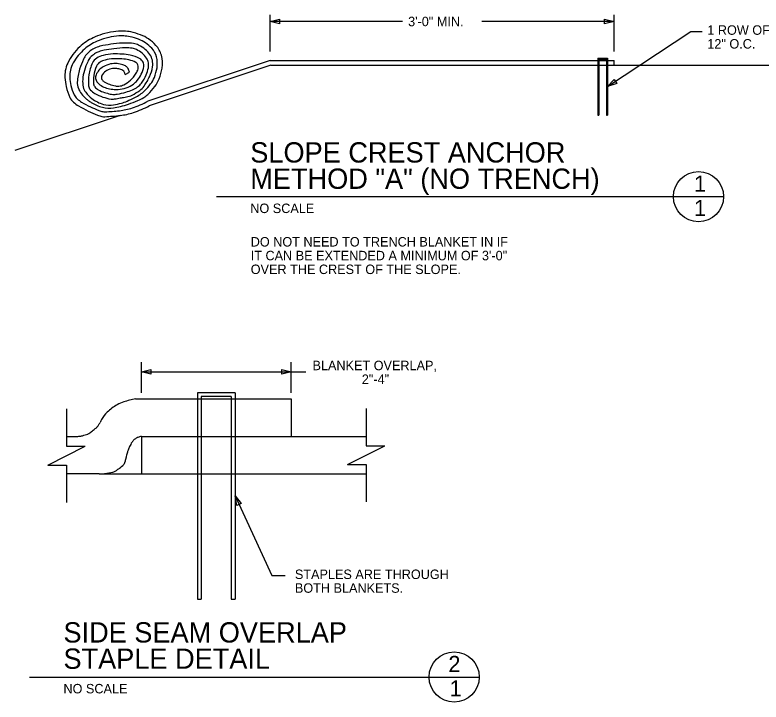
# Model space of a CAD drawing. Extents: x 27123946 to 27124151, y 1145898 to 1146027.
# Drawn here: x 27124034.8 to 27124100.1, y 1145966.8 to 1146026.9 of the extents above; entities that cross this region are included whole.
import ezdxf

# ---------------------------------------------------------------- set-up
doc = ezdxf.new("R2010")
doc.units = 0
for name, color, linetype in [('C-PVMT', 7, 'Continuous'), ('Default', 7, 'Continuous'), ('G-ANNO-CELL', 7, 'Continuous'), ('G-ANNO-TEXT', 7, 'Continuous'), ('G-ANNO-TTXT', 7, 'Continuous'), ('L-SITE-SOIL', 7, 'Continuous')]:
    doc.layers.add(name, color=color, linetype=linetype)

msp = doc.modelspace()

# ---------------------------------------------------------------- linework, layer by layer
at = {"layer": 'C-PVMT'}
for p, q in [((27124057.171, 1146022.891), (27124046.46, 1146019.32)), ((27124057.171, 1146022.891), (27124087.272, 1146022.891)), ((27124087.272, 1146022.474), (27124087.272, 1146022.891)), ((27124057.239, 1146022.474), (27124046.592, 1146018.925)), ((27124057.239, 1146022.474), (27124087.272, 1146022.474)), ((27124087.272, 1146022.474), (27124102.27, 1146022.474)), ((27124045.386, 1145993.286), (27124059.017, 1145993.286)), ((27124059.017, 1145993.286), (27124059.017, 1145990.007)), ((27124039.344, 1145990.007), (27124040.349, 1145990.007)), ((27124045.902, 1145990.007), (27124045.902, 1145986.728)), ((27124045.902, 1145990.007), (27124065.575, 1145990.007)), ((27124042.214, 1145986.728), (27124039.344, 1145986.728)), ((27124045.902, 1145986.728), (27124065.575, 1145986.728))]:
    msp.add_line(p, q, dxfattribs=at)
msp.add_lwpolyline([(27124044.483, 1146021.655), (27124044.849, 1146021.855)], dxfattribs=at)
for centre, radius, start, end in [((27124044.192, 1146020.388), 5.071, 88.01317, 98.4237), ((27124044.253, 1146022.165), 3.292, 77.32435, 88.01317), ((27124043.73, 1146020.422), 4.896, 114.76664, 123.00696), ((27124044.596, 1146018.544), 6.964, 107.85911, 114.76664), ((27124044.353, 1146019.301), 6.17, 98.4237, 107.85911), ((27124044.343, 1146019.319), 5.728, 98.4237, 107.91848), ((27124044.177, 1146020.443), 4.592, 87.81603, 98.4237), ((27124044.234, 1146021.946), 3.088, 77.32435, 87.81603), ((27124043.605, 1146019.151), 5.953, 69.77358, 77.32435), ((27124043.442, 1146018.559), 6.988, 69.99356, 77.32435), ((27124044.773, 1146022.213), 3.1, 55.57154, 69.99356), ((27124043.081, 1146021.421), 3.705, 123.00696, 134.07939), ((27124043.161, 1146021.322), 3.408, 123.04587, 134.07939), ((27124043.716, 1146020.469), 4.427, 114.76664, 123.04587), ((27124044.571, 1146018.617), 6.466, 107.91848, 114.76664), ((27124043.345, 1146020.137), 4.128, 101.30557, 108.71255), ((27124044.996, 1146011.877), 12.551, 97.05967, 101.30557), ((27124044.742, 1146013.929), 10.484, 91.16867, 97.05967), ((27124044.612, 1146020.316), 4.095, 81.73672, 91.16867), ((27124044.984, 1146022.876), 1.508, 63.44395, 81.73672), ((27124044.222, 1146021.353), 3.211, 50.9357, 63.44395), ((27124044.725, 1146022.19), 2.714, 55.57154, 69.77358), ((27124044.441, 1146021.776), 3.216, 42.53148, 55.57154), ((27124044.391, 1146021.655), 3.776, 42.50986, 55.57154), ((27124045.63, 1146022.792), 2.094, 15.07414, 42.50986), ((27124044.593, 1146019.86), 5.879, 134.07939, 142.86493), ((27124044.42, 1146020.022), 5.218, 134.07939, 142.99163), ((27124042.999, 1146021.746), 2.52, 124.95777, 138.85316), ((27124042.613, 1146022.297), 1.847, 108.71255, 124.95777), ((27124042.709, 1146022.16), 1.583, 109.22732, 124.81411), ((27124043.297, 1146020.472), 3.37, 101.30557, 109.22732), ((27124044.963, 1146012.14), 11.868, 97.08628, 101.30557), ((27124044.717, 1146014.117), 9.875, 91.16867, 97.08628), ((27124044.584, 1146020.668), 3.323, 80.95875, 91.16867), ((27124044.908, 1146022.707), 1.259, 63.44395, 80.95875), ((27124044.194, 1146021.279), 2.855, 51.84003, 63.44395), ((27124044.862, 1146022.129), 1.774, 33.18872, 51.84003), ((27124045.006, 1146022.319), 1.967, 33.18872, 50.9357), ((27124045.493, 1146022.74), 1.79, 15.07414, 42.53148), ((27124043.134, 1146020.965), 4.048, 142.86493, 155.21623), ((27124043.175, 1146020.961), 3.659, 142.99163, 155.21623), ((27124046.639, 1146020.26), 6.418, 154.79019, 163.13314), ((27124042.432, 1146022.241), 1.767, 138.85316, 154.79019), ((27124042.521, 1146022.16), 1.457, 138.27281, 154.79019), ((27124043.015, 1146021.72), 2.12, 124.81411, 138.27281), ((27124042.51, 1146022.256), 0.984, 121.665, 154.7137), ((27124043.022, 1146021.425), 1.961, 104.03089, 121.665), ((27124043.104, 1146021.422), 1.548, 104.03089, 121.89178), ((27124043.594, 1146019.136), 4.32, 92.17654, 104.03089), ((27124043.632, 1146019.31), 3.725, 92.54328, 104.03089), ((27124043.696, 1146016.46), 6.998, 85.81664, 92.17654), ((27124043.745, 1146016.772), 6.267, 85.81664, 92.54328), ((27124043.881, 1146018.641), 4.392, 77.78001, 85.81664), ((27124043.754, 1146017.259), 6.197, 79.05759, 85.81664), ((27124044.336, 1146020.739), 2.245, 61.56669, 77.78001), ((27124044.392, 1146020.556), 2.838, 61.56669, 79.05759), ((27124045.386, 1146022.392), 0.751, 27.17705, 61.56669), ((27124045.395, 1146022.477), 1.138, 9.83943, 33.18872), ((27124045.39, 1146022.57), 1.509, 12.9005, 33.18872), ((27124045.406, 1146022.574), 1.493, 350.21375, 12.9005), ((27124045.006, 1146022.609), 2.293, 350.86974, 15.07414), ((27124045.092, 1146022.647), 2.652, 350.74384, 15.07414), ((27124042.039, 1146021.47), 2.842, 155.21623, 169.96936), ((27124042.085, 1146021.464), 2.459, 155.21623, 170.14213), ((27124046.257, 1146020.401), 5.587, 154.79019, 163.20405), ((27124045.016, 1146021.072), 3.756, 154.7137, 171.45509), ((27124044.592, 1146021.156), 2.891, 154.7137, 172.02722), ((27124043.273, 1146021.06), 1.453, 119.22733, 157.15829), ((27124042.719, 1146022.04), 0.821, 121.89178, 154.7137), ((27124043.767, 1146020.179), 2.463, 103.12908, 119.22733), ((27124043.591, 1146020.932), 1.69, 83.66587, 103.12908), ((27124043.575, 1146020.781), 1.411, 82.38454, 103.12908), ((27124043.484, 1146020.101), 2.098, 72.65231, 82.38454), ((27124043.476, 1146019.9), 2.729, 72.65231, 83.66587), ((27124043.996, 1146021.564), 0.985, 54.27413, 72.65231), ((27124044.252, 1146021.92), 0.547, 28.62008, 54.27413), ((27124043.752, 1146021.647), 1.116, 10.7423, 28.62008), ((27124045.192, 1146022.321), 0.447, 24.72089, 61.56669), ((27124044.385, 1146022.445), 1.262, 331.98323, 351.46573), ((27124045.197, 1146022.323), 0.441, 351.46573, 24.72089), ((27124044.05, 1146022.66), 2.09, 331.97737, 351.46573), ((27124045.487, 1146022.444), 0.637, 351.46573, 27.17705), ((27124043.773, 1146022.758), 2.788, 335.97186, 349.37647), ((27124045.33, 1146022.466), 1.204, 349.37647, 9.83943), ((27124043.479, 1146022.906), 3.448, 335.34299, 350.21375), ((27124043.324, 1146022.879), 3.997, 338.42088, 350.86974), ((27124043.18, 1146022.958), 4.589, 338.42088, 350.74384), ((27124041.708, 1146021.529), 2.506, 169.96936, 183.18108), ((27124041.843, 1146021.506), 2.213, 170.14213, 183.18108), ((27124045.334, 1146020.656), 5.054, 163.13314, 176.09788), ((27124044.38, 1146020.968), 3.626, 163.20405, 176.09788), ((27124045.112, 1146021.058), 3.853, 171.45509, 185.71297), ((27124044.728, 1146021.137), 3.029, 172.02722, 185.71297), ((27124042.497, 1146021.387), 0.611, 157.15829, 217.30688), ((27124042.713, 1146021.406), 0.316, 155.54752, 213.89266), ((27124043.32, 1146021.129), 0.984, 123.45944, 155.54752), ((27124043.588, 1146020.725), 1.469, 103.12908, 123.45944), ((27124043.917, 1146021.487), 0.646, 55.06127, 72.65231), ((27124044.069, 1146021.705), 0.38, 28.62008, 55.06127), ((27124043.739, 1146021.525), 0.755, 9.9512, 28.62008), ((27124043.639, 1146022.842), 2.108, 320.99808, 331.98323), ((27124042.966, 1146023.236), 3.318, 320.99808, 331.97737), ((27124042.639, 1146023.263), 4.029, 324.28256, 335.97186), ((27124043.99, 1146021.656), 4.791, 183.18108, 192.72566), ((27124043.738, 1146021.611), 4.111, 183.18108, 192.73794), ((27124041.503, 1146020.917), 1.213, 176.09788, 202.74147), ((27124043.018, 1146021.061), 2.261, 176.09788, 192.44727), ((27124043.152, 1146021.886), 1.434, 217.30688, 236.98642), ((27124043.042, 1146021.627), 0.714, 213.89266, 236.98642), ((27124043.871, 1146022.902), 2.234, 236.98642, 249.97615), ((27124043.074, 1146023.247), 2.799, 297.29053, 311.87733), ((27124042.903, 1146023.438), 3.054, 311.87733, 320.99808), ((27124044.141, 1146022.285), 1.807, 306.10024, 320.99808), ((27124044.778, 1146021.725), 1.395, 304.35108, 324.28256), ((27124041.951, 1146023.607), 5.129, 324.69625, 335.34299), ((27124044.88, 1146022.264), 2.324, 322.07314, 338.42088), ((27124044.851, 1146022.298), 2.792, 322.60426, 338.42088), ((27124043.77, 1146021.606), 4.566, 192.72566, 205.28648), ((27124043.56, 1146021.571), 3.929, 192.73794, 205.28648), ((27124042.469, 1146021.323), 2.261, 202.74147, 216.58396), ((27124042.02, 1146020.84), 1.239, 192.44727, 216.58396), ((27124041.908, 1146020.737), 0.633, 185.71297, 221.37557), ((27124042.641, 1146021.383), 1.61, 221.37557, 240.02803), ((27124042.184, 1146020.882), 0.472, 185.71297, 220.84709), ((27124042.727, 1146021.352), 1.19, 220.84709, 240.02803), ((27124043.481, 1146022.659), 2.699, 240.02803, 252.72996), ((27124043.272, 1146022.072), 1.655, 236.98642, 255.28955), ((27124043.847, 1146024.262), 3.92, 255.28955, 263.48133), ((27124044.313, 1146024.115), 3.525, 249.97615, 258.69431), ((27124043.711, 1146023.071), 2.721, 263.48133, 273.31692), ((27124043.845, 1146021.774), 1.138, 258.69431, 274.06786), ((27124043.719, 1146022.946), 2.596, 273.31692, 289.43288), ((27124043.847, 1146021.75), 1.113, 274.06786, 297.29053), ((27124043.325, 1146024.327), 4.387, 286.19691, 294.29613), ((27124043.774, 1146022.788), 2.428, 289.43288, 306.10024), ((27124043.16, 1146023.847), 4.429, 295.74168, 305.889), ((27124043.958, 1146022.925), 2.849, 294.29613, 304.35108), ((27124044.787, 1146021.599), 1.654, 305.889, 324.69625), ((27124044.498, 1146021.902), 2.37, 303.16369, 314.98885), ((27124041.516, 1146024.886), 6.589, 314.98885, 322.07314), ((27124041.637, 1146024.754), 6.837, 314.98885, 322.60426), ((27124040.81, 1146020.208), 1.293, 205.28648, 229.01589), ((27124041.033, 1146020.377), 1.133, 205.28648, 228.76652), ((27124042.686, 1146021.484), 2.532, 216.58396, 229.66278), ((27124043.205, 1146021.72), 2.715, 216.58396, 232.82115), ((27124043.504, 1146022.88), 3.337, 240.02803, 252.95174), ((27124045.475, 1146029.307), 10.06, 252.95174, 257.20054), ((27124044.603, 1146026.269), 6.479, 252.72996, 257.20054), ((27124043.479, 1146021.324), 1.408, 257.20054, 266.79957), ((27124043.498, 1146021.649), 1.734, 266.79957, 279.72386), ((27124016.101, 1146180.507), 163.31, 279.72386, 279.8907), ((27124042.627, 1146026.731), 6.89, 279.72386, 286.19691), ((27124018.195, 1146168.499), 151.122, 279.8907, 279.96049), ((27123987.161, 1146345.212), 330.539, 279.96049, 280.00768), ((27124044.281, 1146021.523), 1.849, 280.00768, 295.74168), ((27124040.926, 1146028.186), 9.608, 292.78471, 297.2069), ((27124042.897, 1146024.352), 5.297, 297.2069, 303.16369), ((27124043.611, 1146024.022), 5.041, 293.11244, 299.7131), ((27124045.264, 1146021.126), 1.707, 299.7131, 314.98885), ((27124042.017, 1146021.597), 3.133, 229.01589, 239.04615), ((27124042.051, 1146021.539), 2.679, 228.76652, 239.04615), ((27124045.111, 1146026.64), 8.627, 239.04615, 244.76938), ((27124043.511, 1146022.455), 3.806, 229.66278, 233.56372), ((27124044.294, 1146023.516), 5.124, 233.56372, 236.92561), ((27124043.234, 1146021.889), 3.182, 236.92561, 256.43473), ((27124043.454, 1146022.049), 3.128, 232.82115, 253.66996), ((27124043.122, 1146020.915), 1.945, 253.66996, 280.19622), ((27124043.328, 1146019.859), 0.371, 257.20054, 279.45847), ((27124032.784, 1146083.153), 64.537, 279.45847, 279.72386), ((27124042.116, 1146026.506), 7.626, 280.19622, 285.51838), ((27124042.036, 1146027.095), 8.477, 283.85581, 288.77711), ((27124043.062, 1146023.102), 4.094, 285.51838, 292.78471), ((27124041.006, 1146030.127), 11.679, 288.77711, 293.11244), ((27124042.388, 1146026.908), 8.611, 288.43495, 298.21852), ((27124042.331, 1146026.954), 9.09, 288.43495, 297.95272), ((27124045.304, 1146027.077), 9.524, 239.04615, 244.79405), ((27124047.085, 1146030.861), 13.706, 244.79405, 248.50636), ((27124046.652, 1146029.911), 12.243, 244.76938, 248.50636), ((27124043.109, 1146020.914), 2.574, 248.50636, 256.66233), ((27124043.098, 1146021.322), 2.6, 256.43473, 278.04219), ((27124042.689, 1146019.142), 0.752, 256.66233, 273.21119), ((27124041.331, 1146043.338), 24.986, 273.21119, 276.07271), ((27124042.611, 1146024.764), 6.076, 278.04219, 283.85581), ((27124043.403, 1146023.863), 5.401, 276.07271, 288.43495), ((27124043.449, 1146023.601), 5.555, 276.25134, 288.43495), ((27124043.096, 1146020.73), 2.817, 248.50636, 256.70039), ((27124042.649, 1146018.84), 0.875, 256.70039, 273.21119), ((27124041.262, 1146043.568), 25.642, 273.21119, 276.25134), ((27124045.349, 1145989.944), 3.23, 107.88236, 118.9867), ((27124047.226, 1145984.128), 9.341, 101.35922, 107.88236), ((27124045.92, 1145988.913), 4.408, 118.9867, 133.07956), ((27124045.46, 1145989.849), 3.46, 151.7783, 156.60109), ((27124044.626, 1145990.297), 2.514, 133.07956, 151.7783), ((27124041.706, 1145991.138), 0.446, 313.7328, 324.09009), ((27124038.342, 1145993.574), 4.6, 324.09009, 327.31299), ((27124041.427, 1145991.595), 0.934, 327.31299, 336.60109), ((27124038.03, 1146000.005), 10.302, 285.23607, 287.98165), ((27124041.109, 1145990.519), 0.328, 287.98165, 303.40327), ((27124039.374, 1145993.15), 3.48, 303.40327, 307.0537), ((27124035.838, 1145997.833), 9.349, 307.0537, 309.28076), ((27124031.518, 1146003.114), 16.171, 309.28076, 310.22498), ((27124041.204, 1145991.662), 1.172, 310.22498, 313.7328), ((27124040.176, 1145993.307), 3.304, 267.00214, 274.52696), ((27124040.308, 1145991.641), 1.634, 274.52696, 285.23607), ((27124046.206, 1145988.73), 1.359, 133.07956, 145.87858), ((27124045.957, 1145988.996), 0.995, 118.1113, 133.07956), ((27124045.788, 1145989.313), 0.636, 107.88236, 118.1113), ((27124047.165, 1145985.046), 5.12, 104.28124, 107.88236), ((27124046.607, 1145988.246), 1.952, 153.42626, 163.22916), ((27124047.803, 1145987.648), 3.289, 145.87858, 153.42626), ((27124083.189, 1145977.534), 40.07, 164.04872, 164.61514), ((27124063.064, 1145983.286), 19.14, 163.22916, 164.04872), ((27124044.21, 1145987.714), 0.226, 313.25309, 340.78302), ((27124043.155, 1145988.081), 1.343, 340.78302, 348.5958), ((27124049.538, 1145986.794), 5.169, 164.61514, 168.5958), ((27124043.217, 1145987.648), 0.788, 283.23564, 298.63825), ((27124042.889, 1145988.248), 1.473, 298.63825, 304.58173), ((27124040.263, 1145992.057), 6.099, 304.58173, 307.50162), ((27124040.881, 1145991.251), 5.083, 307.50162, 313.25309), ((27124042.364, 1145991.26), 4.535, 268.09976, 271.99129), ((27124042.468, 1145988.272), 1.544, 271.99129, 278.66222), ((27124041.361, 1145995.538), 8.894, 278.66222, 283.23564)]:
    msp.add_arc(centre, radius, start, end, dxfattribs=at)
at = {"layer": 'Default'}
for p, q in [((27124085.863, 1146023.098), (27124086.697, 1146023.098)), ((27124085.863, 1146023.098), (27124085.863, 1146018.092)), ((27124085.946, 1146023.014), (27124085.946, 1146018.092)), ((27124085.946, 1146023.014), (27124086.613, 1146023.014)), ((27124086.613, 1146023.014), (27124086.613, 1146018.092)), ((27124086.697, 1146023.098), (27124086.697, 1146018.092)), ((27124085.863, 1146018.092), (27124085.946, 1146018.092)), ((27124086.613, 1146018.092), (27124086.697, 1146018.092)), ((27124054.099, 1145993.809), (27124050.82, 1145993.809)), ((27124050.82, 1145993.809), (27124050.82, 1145975.776)), ((27124053.771, 1145993.481), (27124051.148, 1145993.481)), ((27124051.148, 1145993.481), (27124051.148, 1145975.776)), ((27124053.771, 1145993.481), (27124053.771, 1145975.776)), ((27124054.099, 1145993.809), (27124054.099, 1145975.776)), ((27124039.344, 1145992.401), (27124039.344, 1145989.137)), ((27124065.575, 1145992.451), (27124065.575, 1145989.187)), ((27124037.705, 1145987.498), (27124040.984, 1145989.137)), ((27124039.344, 1145989.137), (27124040.984, 1145989.137)), ((27124063.935, 1145987.548), (27124067.214, 1145989.187)), ((27124065.575, 1145989.187), (27124067.214, 1145989.187)), ((27124037.705, 1145987.498), (27124039.344, 1145987.498)), ((27124039.344, 1145987.498), (27124039.344, 1145984.235)), ((27124063.935, 1145987.548), (27124065.575, 1145987.548)), ((27124065.575, 1145987.548), (27124065.575, 1145984.285)), ((27124050.82, 1145975.776), (27124051.148, 1145975.776)), ((27124053.771, 1145975.776), (27124054.099, 1145975.776))]:
    msp.add_line(p, q, dxfattribs=at)
at = {"layer": 'G-ANNO-CELL'}
for centre in [(27124094.666, 1146010.973), (27124073.275, 1145968.959)]:
    msp.add_circle(centre, 2.193, dxfattribs=at)
at = {"layer": 'G-ANNO-TEXT'}
for p, q in [((27124057.171, 1146023.672), (27124057.171, 1146026.869)), ((27124087.272, 1146023.672), (27124087.272, 1146026.869)), ((27124068.767, 1146026.301), (27124057.171, 1146026.301)), ((27124087.272, 1146026.301), (27124075.691, 1146026.301)), ((27124086.697, 1146020.595), (27124093.993, 1146025.434)), ((27124093.993, 1146025.434), (27124094.989, 1146025.434)), ((27124052.47, 1146010.973), (27124096.858, 1146010.973)), ((27124045.902, 1145993.827), (27124045.902, 1145996.486)), ((27124059.017, 1145993.827), (27124059.017, 1145996.486)), ((27124045.902, 1145995.654), (27124059.017, 1145995.654)), ((27124059.017, 1145995.654), (27124060.293, 1145995.654)), ((27124054.099, 1145984.792), (27124057.312, 1145977.839)), ((27124057.312, 1145977.839), (27124058.481, 1145977.839)), ((27124036.116, 1145968.959), (27124075.467, 1145968.959))]:
    msp.add_line(p, q, dxfattribs=at)
for points in [[(27124058.004, 1146026.093), (27124057.171, 1146026.301), (27124058.004, 1146026.51)], [(27124086.439, 1146026.51), (27124087.272, 1146026.301), (27124086.439, 1146026.093)], [(27124087.506, 1146020.882), (27124086.697, 1146020.595), (27124087.276, 1146021.229)], [(27124046.735, 1145995.446), (27124045.902, 1145995.654), (27124046.735, 1145995.862)], [(27124058.184, 1145995.862), (27124059.017, 1145995.654), (27124058.184, 1145995.446)], [(27124054.259, 1145983.948), (27124054.099, 1145984.792), (27124054.637, 1145984.123)]]:
    msp.add_lwpolyline(points, close=True, dxfattribs=at)
at = {"layer": 'L-SITE-SOIL'}
for p, q in [((27124044.054, 1146018.079), (27124034.832, 1146015.005)), ((27124042.214, 1145986.728), (27124045.902, 1145986.728))]:
    msp.add_line(p, q, dxfattribs=at)

# ---------------------------------------------------------------- texts
at = {"layer": 'G-ANNO-CELL'}
for s, p in [('1 ', (27124094.276, 1146011.404)), ('1 ', (27124094.276, 1146009.275)), ('2 ', (27124072.774, 1145969.39)), ('1 ', (27124072.885, 1145967.261))]:
    msp.add_text(s, height=1.4167, dxfattribs=at).set_placement(p)
at = {"layer": 'G-ANNO-TEXT'}
for s, p in [('3\'-0" MIN.', (27124069.248, 1146025.882)), ('1 ROW OF STAPLES,', (27124095.435, 1146025.131)), ('12" O.C.', (27124095.435, 1146023.928)), ('NO SCALE', (27124055.434, 1146009.539)), ('DO NOT NEED TO TRENCH BLANKET IN IF ', (27124055.472, 1146006.611)), ('IT CAN BE EXTENDED A MINIMUM OF 3\'-0"', (27124055.472, 1146005.408)), ('OVER THE CREST OF THE SLOPE.', (27124055.472, 1146004.205)), ('BLANKET OVERLAP,', (27124060.88, 1145995.794)), ('2"-4"', (27124065.197, 1145994.591)), ('STAPLES ARE THROUGH', (27124059.338, 1145977.529)), ('BOTH BLANKETS.', (27124059.338, 1145976.326)), ('NO SCALE', (27124039.08, 1145967.525))]:
    msp.add_text(s, height=0.828, dxfattribs=at).set_placement(p)
at = {"layer": 'G-ANNO-TTXT'}
for s, p in [('SLOPE CREST ANCHOR', (27124055.434, 1146013.957)), ('METHOD "A" (NO TRENCH)', (27124055.434, 1146011.658)), ('SIDE SEAM OVERLAP', (27124039.08, 1145971.974)), ('STAPLE DETAIL', (27124039.08, 1145969.675))]:
    msp.add_text(s, height=1.776, dxfattribs=at).set_placement(p)

doc.saveas('drawing.dxf')
